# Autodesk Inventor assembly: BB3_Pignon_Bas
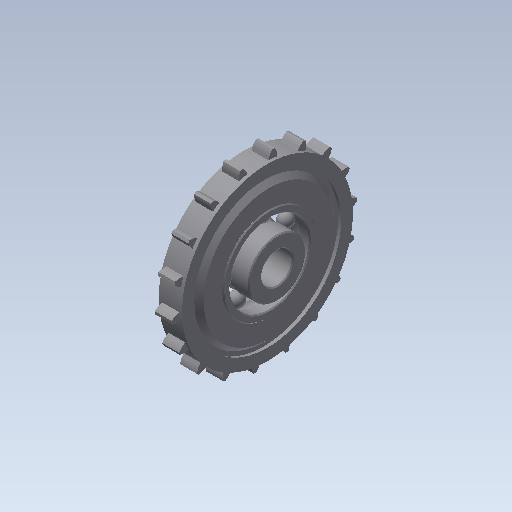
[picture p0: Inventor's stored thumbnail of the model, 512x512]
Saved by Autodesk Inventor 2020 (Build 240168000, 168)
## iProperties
Created: 2008-11
Part Number: BB3_Pignon_Bas
Document SubType Name: Assembly
Designer: LAIVIER CYRIL
Mass: 46.0178 g
Surface Area: 231.044 cm^2
Volume: 46.0178 cm^3
Density: 1 g/cm^3
Author: LAIVIER CYRIL
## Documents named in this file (5)
- D:\Cours\1-Cours-2020-21\1-Site\Elèves\TSTI2D\Tronc-commun\EDC-RDM-Big-Belly\lib\Big-Belly\Big-Belly\BB3_Pignon_Bas.iam
- D:\Cours\1-Cours-2020-21\1-Site\Elèves\TSTI2D\Tronc-commun\EDC-RDM-Big-Belly\lib\Big-Belly\Big-Belly\Pignon_Bas\Bearing_203KRR5.iam
- D:\Cours\1-Cours-2020-21\1-Site\Elèves\TSTI2D\Tronc-commun\EDC-RDM-Big-Belly\lib\Big-Belly\Big-Belly\Pignon_Bas\Pignon_Bas.ipt
- D:\Cours\1-Cours-2020-21\1-Site\Elèves\TSTI2D\Tronc-commun\EDC-RDM-Big-Belly\lib\Big-Belly\Big-Belly\Pignon_Bas\Bearing_203KRR5_BI.ipt
- D:\Cours\1-Cours-2020-21\1-Site\Elèves\TSTI2D\Tronc-commun\EDC-RDM-Big-Belly\lib\Big-Belly\Big-Belly\BB3_Pignon_Cylindre_Primitif.ipt
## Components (4 placed, 4 different names)
1. Bearing_203KRR5:1 [sub-assembly] — Plaquage:1, Plaquage:2
2. Pignon_Bas:1 — Plaquage:1, Plaquage:2, Plaquage:3, Plaquage:4, Plaquage:5, Affleurement:1
3. Bearing_203KRR5_BI:1 — Plaquage:3, Plaquage:4
4. BB3_Pignon_Cylindre_Primitif:1 — Plaquage:5, Affleurement:1
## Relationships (6: Mate 5, Flush 1)
- Plaquage:1 [Mate]: Bearing_203KRR5:1 ↔ Pignon_Bas:1
- Plaquage:2 [Mate]: Bearing_203KRR5:1 ↔ Pignon_Bas:1
- Plaquage:3 [Mate]: Pignon_Bas:1 ↔ Bearing_203KRR5_BI:1
- Plaquage:4 [Mate]: Pignon_Bas:1 ↔ Bearing_203KRR5_BI:1
- Plaquage:5 [Mate]: Pignon_Bas:1 ↔ BB3_Pignon_Cylindre_Primitif:1
- Affleurement:1 [Flush]: Pignon_Bas:1 ↔ BB3_Pignon_Cylindre_Primitif:1
